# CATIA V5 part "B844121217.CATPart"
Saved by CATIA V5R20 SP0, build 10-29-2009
Part number: B844121217
Revision: 3
Definition: design
Nomenclature: B844121217
Source: made
Description: NOT SPECIFIED
Bounding box of the stored display mesh (mm): x -12.5 to 12.5, y -12.5 to 12.5, z -12 to 17
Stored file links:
  C:\Users\Utente\Desktop\3D files B844\B844121217.CATPart
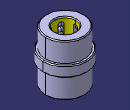
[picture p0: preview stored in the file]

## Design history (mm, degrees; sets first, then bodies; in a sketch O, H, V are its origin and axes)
Body1 "MANIFOLD_SOLID_BREP #38" (main body)
  Solid1: solid without history
Body2 "MANIFOLD_SOLID_BREP #76"
  Solid2: solid without history
Body3 "MANIFOLD_SOLID_BREP #114"
  Solid3: solid without history
Body4 "MANIFOLD_SOLID_BREP #152"
  Solid4: solid without history
Body5 "MANIFOLD_SOLID_BREP #190"
  Solid5: solid without history
Body6 "MANIFOLD_SOLID_BREP #228"
  Solid6: solid without history
Body7 "MANIFOLD_SOLID_BREP #266"
  Solid7: solid without history
Body8 "MANIFOLD_SOLID_BREP #1940"
  Solid8: solid without history
Body9 "MANIFOLD_SOLID_BREP #1978"
  Solid9: solid without history
Body10 "MANIFOLD_SOLID_BREP #2016"
  Solid10: solid without history
Body11 "MANIFOLD_SOLID_BREP #2054"
  Solid11: solid without history
Body12 "MANIFOLD_SOLID_BREP #2092"
  Solid12: solid without history
Body13 "MANIFOLD_SOLID_BREP #2130"
  Solid13: solid without history
Body14 "MANIFOLD_SOLID_BREP #2168"
  Solid14: solid without history
Body15 "MANIFOLD_SOLID_BREP #2206"
  Solid15: solid without history
Body16 "MANIFOLD_SOLID_BREP #2244"
  Solid16: solid without history
Body17 "MANIFOLD_SOLID_BREP #2282"
  Solid17: solid without history
Body18 "MANIFOLD_SOLID_BREP #2320"
  Solid18: solid without history
Body19 "MANIFOLD_SOLID_BREP #2358"
  Solid19: solid without history
Body20 "MANIFOLD_SOLID_BREP #2396"
  Solid20: solid without history
Body21 "MANIFOLD_SOLID_BREP #2434"
  Solid21: solid without history
Body22 "MANIFOLD_SOLID_BREP #2472"
  Solid22: solid without history
Body23 "MANIFOLD_SOLID_BREP #2510"
  Solid23: solid without history
Body24 "MANIFOLD_SOLID_BREP #2548"
  Solid24: solid without history
Body25 "MANIFOLD_SOLID_BREP #2586"
  Solid25: solid without history
Body26 "MANIFOLD_SOLID_BREP #2624"
  Solid26: solid without history
Body27 "MANIFOLD_SOLID_BREP #2662"
  Solid27: solid without history
Body28 "MANIFOLD_SOLID_BREP #2700"
  Solid28: solid without history
Body29 "MANIFOLD_SOLID_BREP #2738"
  Solid29: solid without history
Body30 "MANIFOLD_SOLID_BREP #2776"
  Solid30: solid without history
Body31 "MANIFOLD_SOLID_BREP #2814"
  Solid31: solid without history
Body32 "MANIFOLD_SOLID_BREP #2852"
  Solid32: solid without history
Body33 "MANIFOLD_SOLID_BREP #2890"
  Solid33: solid without history
Body34 "MANIFOLD_SOLID_BREP #2928"
  Solid34: solid without history
Body35 "MANIFOLD_SOLID_BREP #2966"
  Solid35: solid without history
Body36 "MANIFOLD_SOLID_BREP #3004"
  Solid36: solid without history
Body37 "MANIFOLD_SOLID_BREP #3042"
  Solid37: solid without history
Body38 "MANIFOLD_SOLID_BREP #3080"
  Solid38: solid without history
Body39 "MANIFOLD_SOLID_BREP #3118"
  Solid39: solid without history
Body40 "MANIFOLD_SOLID_BREP #3156"
  Solid40: solid without history
Body41 "MANIFOLD_SOLID_BREP #3194"
  Solid41: solid without history
Body42 "MANIFOLD_SOLID_BREP #3232"
  Solid42: solid without history
Body43 "MANIFOLD_SOLID_BREP #3270"
  Solid43: solid without history
Body44 "MANIFOLD_SOLID_BREP #3308"
  Solid44: solid without history
Body45 "MANIFOLD_SOLID_BREP #3346"
  Solid45: solid without history
Body46 "MANIFOLD_SOLID_BREP #3384"
  Solid46: solid without history
Body47 "MANIFOLD_SOLID_BREP #3422"
  Solid47: solid without history
Body48 "MANIFOLD_SOLID_BREP #3460"
  Solid48: solid without history
Body49 "MANIFOLD_SOLID_BREP #3498"
  Solid49: solid without history
Body50 "MANIFOLD_SOLID_BREP #3536"
  Solid50: solid without history
Body51 "MANIFOLD_SOLID_BREP #3574"
  Solid51: solid without history
Body52 "MANIFOLD_SOLID_BREP #3612"
  Solid52: solid without history
Body53 "MANIFOLD_SOLID_BREP #3650"
  Solid53: solid without history
Body54 "MANIFOLD_SOLID_BREP #3688"
  Solid54: solid without history
Body55 "MANIFOLD_SOLID_BREP #3726"
  Solid55: solid without history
